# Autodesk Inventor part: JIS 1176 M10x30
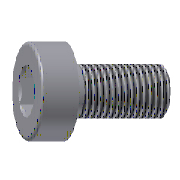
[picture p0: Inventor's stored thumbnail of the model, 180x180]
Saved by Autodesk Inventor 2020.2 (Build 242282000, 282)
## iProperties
Created: 2019-01
Part Number: JIS 1176 M10x30
Material: Stal, miękka
Description: Wkręt z łbem półkolistym walcowym
Document SubType Name: Modeling
Designer: F.Stasiak
Standard Revision: 1
Language: pl-PL
Size Designation: M10x30
Categories: <MemberInstance><Categories><Category DisplayName="Forma wtryskowa" InternalName="349578f2-f4d4-4954-8c09-8e99297a61c0" Mnemonic="MOLD"><Category DisplayName="C
Mass: 0.133121 g
Surface Area: 2.01441 cm^2
Volume: 0.133121 cm^3
Density: 7.85 g/cm^3
Appearance: Częściowo polerowany
Catalog Web Link: www.expertbooks.pl
Manager: www.cadconsulting.pl
Company: Fabian Stasiak CAD Consulting
IsCustomPart: 0
Author: F.Stasiak
Subject: Zbiór ćwiczeń. Autodesk Inventor 2020. Kurs Professional
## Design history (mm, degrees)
body "Solid1"
revolve "Obrót1" stored, may be unused: angle "d44" = 90 deg
sketch "Sketch2"
  geometry: L1 (0, 4.619)-(4, 2.309); L2 (4, 2.309)-(4, -2.309); L3 (4, -2.309)-(0, -4.619); L4 (0, -4.619)-(-4, -2.309); L5 (-4, -2.309)-(-4, 2.309); L6 (-4, 2.309)-(0, 4.619); 3 further points
  constraints: 12 end point, 2 vertical alignment, 1 coincident, 14 other
extrude "Wyciągnięcie proste1" cut sketch "Sketch2" taper "d9" = 0 deg; stored distance "d45" = 10
feature "Gwint1" dims "d10" = 26.25 (= b), "d11" = 0
chamfer "Faza1" distance "d12" = 0.75 (= 0.5 x P); stored, may be unused: second distance "d50" = 2, angle "d51" = 45 deg
fillet "Zaokrąglenie1" dims "d13" = 0.75 (= 0.5 x P)
sketch "Sketch1"
  geometry: L1 (0, -38)-(0, 18) reference; L2 (4.619, 10)-(8, 10); L3 (8, 10)-(8, 0); L4 (8, 0)-(5, 0); L5 (5, 0)-(5, -30); L6 (5, -30)-(0, -30); L7 (0, 2.597)-(0, -30); L8 (0, 2.597)-(4, 5); L9 (4, 5)-(4, 9.381); L10 (4, 9.381)-(4.619, 10); 1 further point
  constraints: 18 end point, 4 vertical, 3 horizontal, 2 point on line
  dimensions: "d0" = 16 diameter of L3 L1 (= dk); "d1" = 10 distance between parallel lines of L4 L2 (= k); "d2" = 10 diameter of L5 L1 (= d); "d3" = 30 distance between parallel lines of L6 L4 (= L); "d4" = 59 deg angle of L1 L8; "d5" = 45 deg angle of L1 L10; "d6" = 8 diameter of L9 L1 (= sw); "d7" = 9.2376 diameter of L2.start L1 (= 1.1547 x sw); "d8" = 5 distance from line of L8.end L2 (= t)
other parameters: "d" = 10 [user parameter; used in 1 equation term], "L" = 30 [user parameter; used in 1 equation term], "dk" = 16 [user parameter; used in 1 equation term], "b" = 26.25 [user parameter; used in 1 equation term], "k" = 10 [user parameter; used in 1 equation term], "sw" = 8 [user parameter; used in 2 equation terms], "t" = 5 [user parameter; used in 1 equation term], "P" = 1.5 [user parameter; used in 2 equation terms], "d14" = 0, "d15" = 0, "d55" = 0
